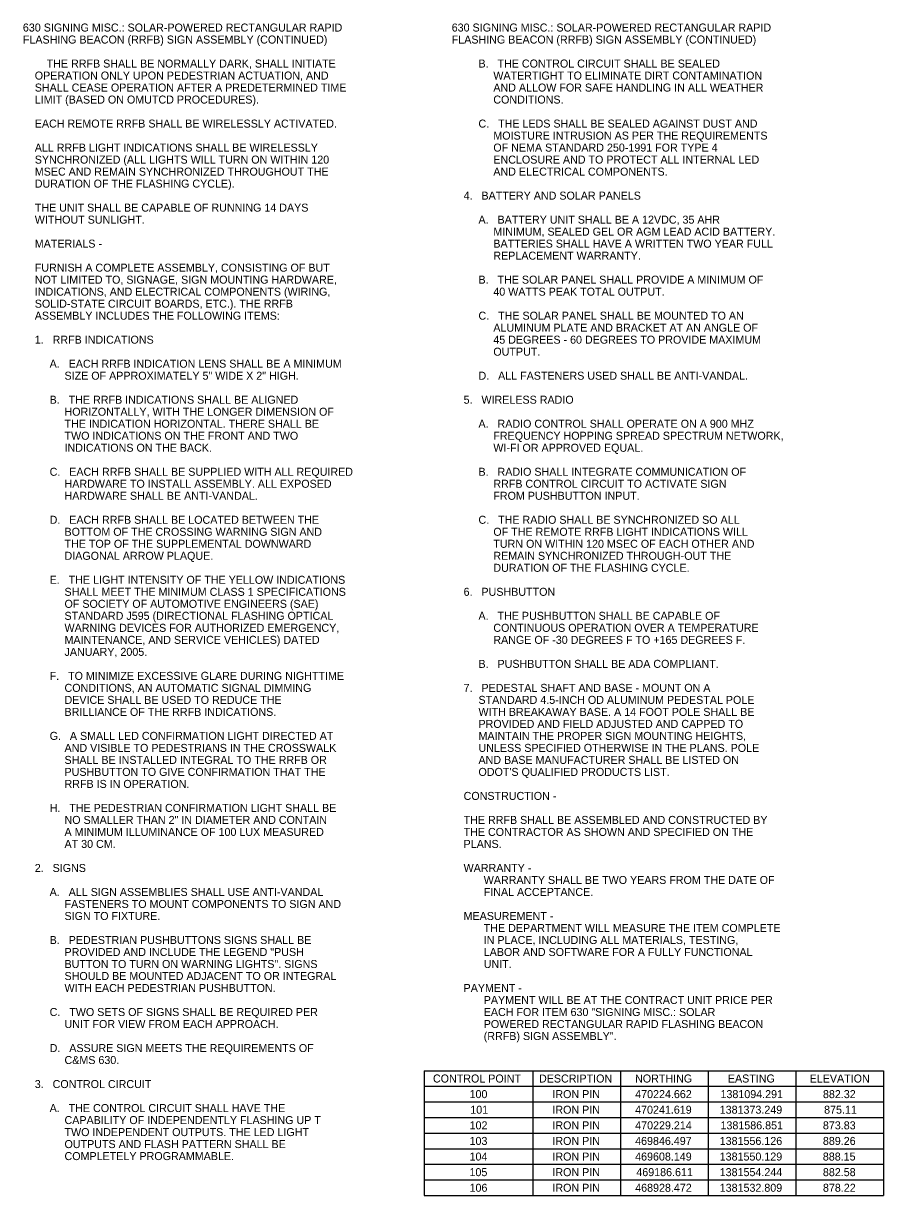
# Model space of a CAD drawing. Extents: x -8.5 to 44.5, y -30.9 to 22.
# Drawn here: x 16.44 to 31.48, y -30.87 to -10.37 of the extents above; entities that cross this region are included whole.
import ezdxf

# ---------------------------------------------------------------- set-up
doc = ezdxf.new("R2010")
doc.units = 0
doc.layers.add('SV_X_Random_Point', color=7, linetype='Continuous')

msp = doc.modelspace()

# ---------------------------------------------------------------- linework, layer by layer
at = {"layer": 'SV_X_Random_Point'}
for p, q in [((23.451, -28.687), (31.484, -28.687)), ((23.451, -28.687), (23.451, -30.871)), ((25.352, -28.687), (25.352, -30.871)), ((26.885, -28.687), (26.885, -30.871)), ((28.418, -28.687), (28.418, -30.871)), ((29.951, -28.687), (29.951, -30.871)), ((31.484, -28.687), (31.484, -30.871)), ((23.451, -28.96), (31.484, -28.96)), ((23.451, -29.233), (31.484, -29.233)), ((23.451, -29.506), (31.484, -29.506)), ((23.451, -29.779), (31.484, -29.779)), ((23.451, -30.052), (31.484, -30.052)), ((23.451, -30.325), (31.484, -30.325)), ((23.451, -30.598), (31.484, -30.598)), ((23.451, -30.871), (31.484, -30.871))]:
    msp.add_line(p, q, dxfattribs=at)

# ---------------------------------------------------------------- texts
for s, p in [('630 SIGNING MISC.: SOLAR-POWERED RECTANGULAR RAPID', (16.431, -10.511)), ('630 SIGNING MISC.: SOLAR-POWERED RECTANGULAR RAPID', (23.931, -10.511)), ('FLASHING BEACON (RRFB) SIGN ASSEMBLY (CONTINUED)', (16.431, -10.721)), ('FLASHING BEACON (RRFB) SIGN ASSEMBLY (CONTINUED)', (23.931, -10.721)), ('        THE RRFB SHALL BE NORMALLY DARK, SHALL INITIATE', (16.431, -11.141)), ('         B.   THE CONTROL CIRCUIT SHALL BE SEALED', (23.931, -11.141)), ('    OPERATION ONLY UPON PEDESTRIAN ACTUATION, AND', (16.431, -11.351)), ('              WATERTIGHT TO ELIMINATE DIRT CONTAMINATION', (23.931, -11.351)), ('    SHALL CEASE OPERATION AFTER A PREDETERMINED TIME', (16.431, -11.561)), ('              AND ALLOW FOR SAFE HANDLING IN ALL WEATHER', (23.931, -11.561)), ('    LIMIT (BASED ON OMUTCD PROCEDURES).', (16.431, -11.771)), ('              CONDITIONS.', (23.931, -11.771)), ('    EACH REMOTE RRFB SHALL BE WIRELESSLY ACTIVATED.', (16.431, -12.191)), ('         C.   THE LEDS SHALL BE SEALED AGAINST DUST AND', (23.931, -12.191)), ('              MOISTURE INTRUSION AS PER THE REQUIREMENTS', (23.931, -12.401)), ('    ALL RRFB LIGHT INDICATIONS SHALL BE WIRELESSLY', (16.431, -12.611)), ('              OF NEMA STANDARD 250-1991 FOR TYPE 4', (23.931, -12.611)), ('    SYNCHRONIZED (ALL LIGHTS WILL TURN ON WITHIN 120', (16.431, -12.821)), ('              ENCLOSURE AND TO PROTECT ALL INTERNAL LED', (23.931, -12.821)), ('    MSEC AND REMAIN SYNCHRONIZED THROUGHOUT THE', (16.431, -13.031)), ('              AND ELECTRICAL COMPONENTS.', (23.931, -13.031)), ('    DURATION OF THE FLASHING CYCLE).', (16.431, -13.241)), ('    4.   BATTERY AND SOLAR PANELS', (23.931, -13.451)), ('    THE UNIT SHALL BE CAPABLE OF RUNNING 14 DAYS', (16.431, -13.661)), ('    WITHOUT SUNLIGHT.', (16.431, -13.871)), ('         A.   BATTERY UNIT SHALL BE A 12VDC, 35 AHR', (23.931, -13.871)), ('              MINIMUM, SEALED GEL OR AGM LEAD ACID BATTERY.', (23.931, -14.081)), ('    MATERIALS -', (16.431, -14.291)), ('              BATTERIES SHALL HAVE A WRITTEN TWO YEAR FULL', (23.931, -14.291)), ('              REPLACEMENT WARRANTY.', (23.931, -14.501)), ('    FURNISH A COMPLETE ASSEMBLY, CONSISTING OF BUT', (16.431, -14.711)), ('    NOT LIMITED TO, SIGNAGE, SIGN MOUNTING HARDWARE,', (16.431, -14.921)), ('         B.   THE SOLAR PANEL SHALL PROVIDE A MINIMUM OF', (23.931, -14.921)), ('    INDICATIONS, AND ELECTRICAL COMPONENTS (WIRING,', (16.431, -15.131)), ('              40 WATTS PEAK TOTAL OUTPUT.', (23.931, -15.131)), ('    SOLID-STATE CIRCUIT BOARDS, ETC.). THE RRFB', (16.431, -15.341)), ('    ASSEMBLY INCLUDES THE FOLLOWING ITEMS:', (16.431, -15.551)), ('         C.   THE SOLAR PANEL SHALL BE MOUNTED TO AN', (23.931, -15.551)), ('              ALUMINUM PLATE AND BRACKET AT AN ANGLE OF', (23.931, -15.761)), ('    1.   RRFB INDICATIONS', (16.431, -15.971)), ('              45 DEGREES - 60 DEGREES TO PROVIDE MAXIMUM', (23.931, -15.971)), ('              OUTPUT.', (23.931, -16.181)), ('         A.   EACH RRFB INDICATION LENS SHALL BE A MINIMUM', (16.431, -16.391)), ('              SIZE OF APPROXIMATELY 5" WIDE X 2" HIGH.', (16.431, -16.601)), ('         D.   ALL FASTENERS USED SHALL BE ANTI-VANDAL.', (23.931, -16.601)), ('         B.   THE RRFB INDICATIONS SHALL BE ALIGNED', (16.431, -17.021)), ('    5.   WIRELESS RADIO', (23.931, -17.021)), ('              HORIZONTALLY, WITH THE LONGER DIMENSION OF', (16.431, -17.231)), ('              THE INDICATION HORIZONTAL. THERE SHALL BE', (16.431, -17.441)), ('         A.   RADIO CONTROL SHALL OPERATE ON A 900 MHZ', (23.931, -17.441)), ('              TWO INDICATIONS ON THE FRONT AND TWO', (16.431, -17.651)), ('              FREQUENCY HOPPING SPREAD SPECTRUM NETWORK,', (23.931, -17.651)), ('              INDICATIONS ON THE BACK.', (16.431, -17.861)), ('              WI-FI OR APPROVED EQUAL.', (23.931, -17.861)), ('         C.   EACH RRFB SHALL BE SUPPLIED WITH ALL REQUIRED', (16.431, -18.281)), ('         B.   RADIO SHALL INTEGRATE COMMUNICATION OF', (23.931, -18.281)), ('              HARDWARE TO INSTALL ASSEMBLY. ALL EXPOSED', (16.431, -18.491)), ('              RRFB CONTROL CIRCUIT TO ACTIVATE SIGN', (23.931, -18.491)), ('              HARDWARE SHALL BE ANTI-VANDAL.', (16.431, -18.701)), ('              FROM PUSHBUTTON INPUT.', (23.931, -18.701)), ('         D.   EACH RRFB SHALL BE LOCATED BETWEEN THE', (16.431, -19.121)), ('         C.   THE RADIO SHALL BE SYNCHRONIZED SO ALL', (23.931, -19.121)), ('              BOTTOM OF THE CROSSING WARNING SIGN AND', (16.431, -19.331)), ('              OF THE REMOTE RRFB LIGHT INDICATIONS WILL', (23.931, -19.331)), ('              THE TOP OF THE SUPPLEMENTAL DOWNWARD', (16.431, -19.541)), ('              TURN ON WITHIN 120 MSEC OF EACH OTHER AND', (23.931, -19.541)), ('              DIAGONAL ARROW PLAQUE.', (16.431, -19.751)), ('              REMAIN SYNCHRONIZED THROUGH-OUT THE', (23.931, -19.751)), ('              DURATION OF THE FLASHING CYCLE.', (23.931, -19.961)), ('         E.   THE LIGHT INTENSITY OF THE YELLOW INDICATIONS', (16.431, -20.171)), ('              SHALL MEET THE MINIMUM CLASS 1 SPECIFICATIONS', (16.431, -20.381)), ('    6.   PUSHBUTTON', (23.931, -20.381)), ('              OF SOCIETY OF AUTOMOTIVE ENGINEERS (SAE)', (16.431, -20.591)), ('              STANDARD J595 (DIRECTIONAL FLASHING OPTICAL', (16.431, -20.801)), ('         A.   THE PUSHBUTTON SHALL BE CAPABLE OF', (23.931, -20.801)), ('              WARNING DEVICES FOR AUTHORIZED EMERGENCY,', (16.431, -21.011)), ('              CONTINUOUS OPERATION OVER A TEMPERATURE', (23.931, -21.011)), ('              MAINTENANCE, AND SERVICE VEHICLES) DATED', (16.431, -21.221)), ('              RANGE OF -30 DEGREES F TO +165 DEGREES F.', (23.931, -21.221)), ('              JANUARY, 2005.', (16.431, -21.431)), ('         B.   PUSHBUTTON SHALL BE ADA COMPLIANT.', (23.931, -21.641)), ('         F.   TO MINIMIZE EXCESSIVE GLARE DURING NIGHTTIME', (16.431, -21.851)), ('              CONDITIONS, AN AUTOMATIC SIGNAL DIMMING', (16.431, -22.061)), ('    7.   PEDESTAL SHAFT AND BASE - MOUNT ON A', (23.931, -22.061)), ('              DEVICE SHALL BE USED TO REDUCE THE', (16.431, -22.271)), ('         STANDARD 4.5-INCH OD ALUMINUM PEDESTAL POLE', (23.931, -22.271)), ('              BRILLIANCE OF THE RRFB INDICATIONS.', (16.431, -22.481)), ('         WITH BREAKAWAY BASE. A 14 FOOT POLE SHALL BE', (23.931, -22.481)), ('         PROVIDED AND FIELD ADJUSTED AND CAPPED TO', (23.931, -22.691)), ('         G.   A SMALL LED CONFIRMATION LIGHT DIRECTED AT', (16.431, -22.901)), ('         MAINTAIN THE PROPER SIGN MOUNTING HEIGHTS,', (23.931, -22.901)), ('              AND VISIBLE TO PEDESTRIANS IN THE CROSSWALK', (16.431, -23.111)), ('         UNLESS SPECIFIED OTHERWISE IN THE PLANS. POLE', (23.931, -23.111)), ('              SHALL BE INSTALLED INTEGRAL TO THE RRFB OR', (16.431, -23.321)), ('         AND BASE MANUFACTURER SHALL BE LISTED ON', (23.931, -23.321)), ('              PUSHBUTTON TO GIVE CONFIRMATION THAT THE', (16.431, -23.531)), ("         ODOT'S QUALIFIED PRODUCTS LIST.", (23.931, -23.531)), ('              RRFB IS IN OPERATION.', (16.431, -23.741)), ('    CONSTRUCTION -', (23.931, -23.951)), ('         H.   THE PEDESTRIAN CONFIRMATION LIGHT SHALL BE', (16.431, -24.161)), ('              NO SMALLER THAN 2" IN DIAMETER AND CONTAIN', (16.431, -24.371)), ('    THE RRFB SHALL BE ASSEMBLED AND CONSTRUCTED BY', (23.931, -24.371)), ('              A MINIMUM ILLUMINANCE OF 100 LUX MEASURED', (16.431, -24.581)), ('    THE CONTRACTOR AS SHOWN AND SPECIFIED ON THE', (23.931, -24.581)), ('              AT 30 CM.', (16.431, -24.791)), ('    PLANS.', (23.931, -24.791)), ('    2.   SIGNS', (16.431, -25.211)), ('    WARRANTY -', (23.931, -25.211)), ('WARRANTY SHALL BE TWO YEARS FROM THE DATE OF', (24.491, -25.421)), ('         A.   ALL SIGN ASSEMBLIES SHALL USE ANTI-VANDAL', (16.431, -25.631)), ('FINAL ACCEPTANCE.', (24.491, -25.631)), ('              FASTENERS TO MOUNT COMPONENTS TO SIGN AND', (16.431, -25.841)), ('              SIGN TO FIXTURE.', (16.431, -26.051)), ('    MEASUREMENT -', (23.931, -26.051)), ('THE DEPARTMENT WILL MEASURE THE ITEM COMPLETE', (24.491, -26.261)), ('         B.   PEDESTRIAN PUSHBUTTONS SIGNS SHALL BE', (16.431, -26.471)), ('IN PLACE, INCLUDING ALL MATERIALS, TESTING,', (24.491, -26.471)), ('              PROVIDED AND INCLUDE THE LEGEND "PUSH', (16.431, -26.681)), ('LABOR AND SOFTWARE FOR A FULLY FUNCTIONAL', (24.491, -26.681)), ('              BUTTON TO TURN ON WARNING LIGHTS". SIGNS', (16.431, -26.891)), ('UNIT.', (24.491, -26.891)), ('              SHOULD BE MOUNTED ADJACENT TO OR INTEGRAL', (16.431, -27.101)), ('              WITH EACH PEDESTRIAN PUSHBUTTON.', (16.431, -27.311)), ('    PAYMENT -', (23.931, -27.311)), ('PAYMENT WILL BE AT THE CONTRACT UNIT PRICE PER', (24.491, -27.521)), ('         C.   TWO SETS OF SIGNS SHALL BE REQUIRED PER', (16.431, -27.731)), ('EACH FOR ITEM 630 "SIGNING MISC.: SOLAR', (24.491, -27.731)), ('              UNIT FOR VIEW FROM EACH APPROACH.', (16.431, -27.941)), ('POWERED RECTANGULAR RAPID FLASHING BEACON', (24.491, -27.941)), ('(RRFB) SIGN ASSEMBLY".', (24.491, -28.151)), ('         D.   ASSURE SIGN MEETS THE REQUIREMENTS OF', (16.431, -28.361)), ('              C&MS 630.', (16.431, -28.571)), ('    3.   CONTROL CIRCUIT', (16.431, -28.991)), ('CONTROL POINT', (23.603, -28.894)), ('DESCRIPTION', (25.458, -28.894)), ('NORTHING', (27.138, -28.894)), ('EASTING', (28.761, -28.894)), ('ELEVATION', (30.191, -28.894)), ('100', (24.243, -29.167)), ('IRON PIN', (25.692, -29.167)), ('470224.662', (27.14, -29.167)), ('1381094.291', (28.632, -29.167)), ('882.32', (30.424, -29.167)), ('         A.   THE CONTROL CIRCUIT SHALL HAVE THE', (16.431, -29.411)), ('101', (24.256, -29.44)), ('IRON PIN', (25.692, -29.44)), ('470241.619', (27.139, -29.44)), ('1381373.249', (28.618, -29.44)), ('875.11', (30.444, -29.44)), ('              CAPABILITY OF INDEPENDENTLY FLASHING UP T', (16.431, -29.621)), ('              TWO INDEPENDENT OUTPUTS. THE LED LIGHT', (16.431, -29.831)), ('102', (24.244, -29.713)), ('IRON PIN', (25.692, -29.713)), ('470229.214', (27.14, -29.713)), ('1381586.851', (28.632, -29.713)), ('873.83', (30.423, -29.713)), ('              OUTPUTS AND FLASH PATTERN SHALL BE', (16.431, -30.041)), ('103', (24.243, -29.986)), ('IRON PIN', (25.692, -29.986)), ('469846.497', (27.139, -29.986)), ('1381556.126', (28.618, -29.986)), ('889.26', (30.423, -29.986)), ('              COMPLETELY PROGRAMMABLE.', (16.431, -30.251)), ('104', (24.243, -30.259)), ('IRON PIN', (25.692, -30.259)), ('469608.149', (27.139, -30.259)), ('1381550.129', (28.618, -30.259)), ('888.15', (30.422, -30.259)), ('105', (24.242, -30.532)), ('IRON PIN', (25.692, -30.532)), ('469186.611', (27.16, -30.532)), ('1381554.244', (28.618, -30.532)), ('882.58', (30.423, -30.532)), ('106', (24.243, -30.805)), ('IRON PIN', (25.692, -30.805)), ('468928.472', (27.14, -30.805)), ('1381532.809', (28.618, -30.805)), ('878.22', (30.424, -30.805))]:
    msp.add_text(s, height=0.14, dxfattribs=at).set_placement(p)

doc.saveas('drawing.dxf')
